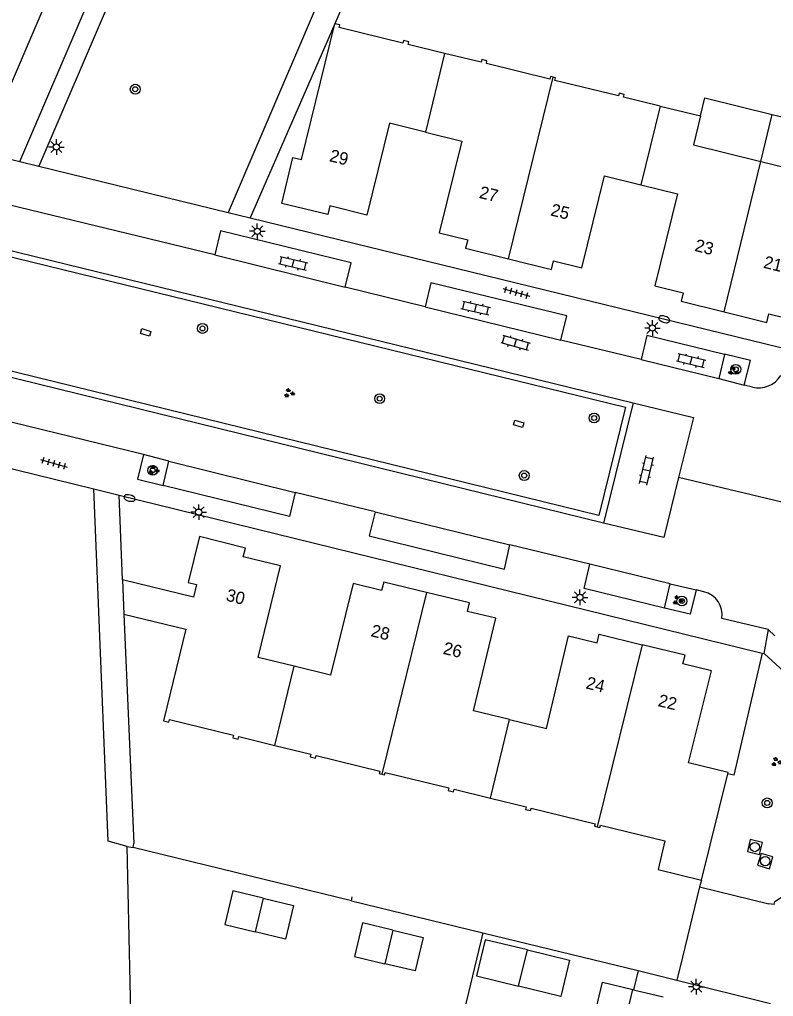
# Model space of a CAD drawing. Extents: x 125000 to 129004, y 397500 to 399008.
# Drawn here: x 126498.7 to 126559.6, y 398186.4 to 398265.2 of the extents above; entities that cross this region are included whole.
import ezdxf

# ---------------------------------------------------------------- set-up
doc = ezdxf.new("R2010")
doc.units = 0
for name, color, linetype in [('gg-afsc-erfafscheiding', 7, 'Continuous'), ('gg-afsc-hekwerk', 7, 'Continuous'), ('gg-afsc-muur', 7, 'Continuous'), ('gg-anno-huisnummerreeks BGT', 7, 'Continuous'), ('gg-bbg-bijgebouw', 7, 'Continuous'), ('gg-bbg-gedigitaliseerde bijgebouw', 7, 'Continuous'), ('gg-bbg-hoofdgebouw', 7, 'Continuous'), ('gg-bbg-luifel en loopbrug', 7, 'Continuous'), ('gg-bbg-tussenscheiding', 7, 'Continuous'), ('gg-knt-verharding', 7, 'Continuous'), ('gg-knt-verharding nz', 7, 'Continuous'), ('gt-grn-groengrens', 7, 'Continuous'), ('gt-grn-weggrens', 7, 'Continuous'), ('gt-symb-boom', 7, 'Continuous'), ('gt-symb-brandkraan', 7, 'Continuous'), ('gt-symb-groenvak', 7, 'Continuous'), ('gt-symb-klinker verharding', 7, 'Continuous'), ('gt-symb-kolk center center', 7, 'Continuous'), ('gt-symb-lichtmast', 7, 'Continuous'), ('gt-symb-rioolschacht', 7, 'Continuous'), ('gt-symb-tegel verharding', 7, 'Continuous')]:
    doc.layers.add(name, color=color, linetype=linetype)

# ---------------------------------------------------------------- blocks, each defined once
blk = doc.blocks.new('gt0-LMAST')
at = {"layer": 'gt-symb-lichtmast'}
for p, q in [((-0.182, 0.173), (-0.447, 0.438)), ((-0.005, 0.246), (-0.005, 0.621)), ((0.172, 0.173), (0.437, 0.438)), ((-0.255, -0.004), (-0.63, -0.004)), ((-0.182, -0.181), (-0.447, -0.446)), ((-0.005, -0.254), (-0.005, -0.629)), ((0.437, -0.446), (0.172, -0.181)), ((0.245, -0.004), (0.62, -0.004))]:
    blk.add_line(p, q, dxfattribs=at)
blk.add_circle((-0.005, -0.004), 0.25, dxfattribs=at)
blk = doc.blocks.new('gt0-KL1')
at = {"layer": 'gt-symb-klinker verharding'}
for p, q in [((-1.15, 0.3), (1.15, 0.3)), ((-1, -0.3), (-1, 0.3)), ((-0.5, 0.3), (-0.5, 0.45)), ((0, -0.3), (0, 0.3)), ((0.5, 0.3), (0.5, 0.45)), ((1, -0.3), (1, 0.3)), ((-1.15, -0.3), (1.15, -0.3)), ((-0.5, -0.45), (-0.5, -0.3)), ((0.5, -0.45), (0.5, -0.3))]:
    blk.add_line(p, q, dxfattribs=at)
blk = doc.blocks.new('gt0-GRVAK')
at = {"layer": 'gt-symb-groenvak'}
for p, q in [((-0.11, 0.189), (-0.228, 0.24)), ((-0.182, 0.153), (0.088, 0.153)), ((-0.091, 0.211), (-0.156, 0.322)), ((-0.047, 0.214), (-0.047, 0.393)), ((-0.004, 0.211), (0.061, 0.322)), ((0.015, 0.189), (0.133, 0.24)), ((0.262, -0.052), (0.197, 0.059)), ((0.305, -0.049), (0.305, 0.13)), ((0.349, -0.052), (0.414, 0.059)), ((-0.245, -0.228), (-0.363, -0.177)), ((-0.318, -0.264), (-0.047, -0.264)), ((-0.226, -0.206), (-0.291, -0.095)), ((-0.183, -0.203), (-0.183, -0.024)), ((-0.139, -0.206), (-0.074, -0.095)), ((-0.12, -0.228), (-0.002, -0.177)), ((0.243, -0.074), (0.125, -0.023)), ((0.17, -0.11), (0.441, -0.11)), ((0.368, -0.074), (0.486, -0.023))]:
    blk.add_line(p, q, dxfattribs=at)
blk = doc.blocks.new('gt0-BOOM')
at = {"layer": 'gt-symb-boom'}
for radius in [0.4, 0.2]:
    blk.add_circle((0, 0), radius, dxfattribs=at)
blk = doc.blocks.new('gt0-RS')
at = {"layer": 'gt-symb-rioolschacht'}
blk.add_lwpolyline([(-0.5, -0.5), (0.5, -0.5), (0.5, 0.5), (-0.5, 0.5)], close=True, dxfattribs=at)
blk.add_circle((0, 0), 0.375, dxfattribs=at)
blk = doc.blocks.new('gt0-KOLKCC')
at = {"layer": 'gt-symb-kolk center center'}
blk.add_lwpolyline([(-0.375, 0.2), (0.375, 0.2), (0.375, -0.2), (-0.375, -0.2)], close=True, dxfattribs=at)
blk = doc.blocks.new('gt0-BR')
at = {"layer": 'gt-symb-brandkraan'}
for centre, radius, start, end in [((-0.244, 0), 0.206, 107.56694, 252.43307), ((0.599, -2.664), 3, 106.89205, 107.56694), ((0, -0.691), 0.938, 73.10799, 106.89205), ((-0.599, -2.664), 3, 72.43309, 73.10799), ((0.244, 0), 0.206, 287.56695, 72.43309), ((0.599, 2.664), 3, 252.43307, 253.10797), ((0, 0.691), 0.938, 253.10797, 286.89206), ((-0.599, 2.664), 3, 286.89206, 287.56695)]:
    blk.add_arc(centre, radius, start, end, dxfattribs=at)
blk = doc.blocks.new('gt0-TEG1')
at = {"layer": 'gt-symb-tegel verharding'}
for p, q in [((-1.125, 0), (1.125, 0)), ((-0.9, -0.25), (-0.9, 0.25)), ((-0.45, -0.25), (-0.45, 0.25)), ((0, -0.25), (0, 0.25)), ((0.45, -0.25), (0.45, 0.25)), ((0.9, -0.25), (0.9, 0.25))]:
    blk.add_line(p, q, dxfattribs=at)

msp = doc.modelspace()

# ---------------------------------------------------------------- linework, layer by layer
at = {"layer": 'gg-afsc-erfafscheiding'}
for p, q in [((126530.085, 398278.427), (126524.158, 398264.837)), ((126524.158, 398264.837), (126517.334, 398249.183)), ((126507.141, 398217.221), (126507.957, 398198.733)), ((126558.655, 398214.074), (126556.351, 398204.237)), ((126507.415, 398198.481), (126507.893, 398198.414)), ((126525.501, 398194.112), (126536.118, 398191.524)), ((126536.118, 398191.524), (126530.205, 398167.154)), ((126536.118, 398191.524), (126548.626, 398188.475)), ((126548.626, 398188.475), (126548.275, 398186.937)), ((126548.626, 398188.475), (126551.761, 398187.711))]:
    msp.add_line(p, q, dxfattribs=at)
msp.add_lwpolyline([(126507.32, 398172.797), (126506.054, 398173.108), (126505.732, 398184.245), (126507.749, 398183.848), (126507.415, 398198.481)], dxfattribs=at)
at = {"layer": 'gg-afsc-hekwerk'}
for p, q in [((126556.351, 398204.237), (126555.863, 398204.347)), ((126553.736, 398195.771), (126553.6, 398195.242)), ((126553.6, 398195.242), (126552.211, 398189.553)), ((126553.6, 398195.242), (126559.178, 398193.847)), ((126552.211, 398189.553), (126551.761, 398187.711)), ((126551.761, 398187.711), (126559.318, 398185.826))]:
    msp.add_line(p, q, dxfattribs=at)
at = {"layer": 'gg-afsc-muur'}
for p, q in [((126507.036, 398219.989), (126506.755, 398226.822)), ((126507.893, 398198.414), (126507.957, 398198.733)), ((126525.501, 398194.112), (126507.893, 398198.414)), ((126525.501, 398194.112), (126525.565, 398194.431))]:
    msp.add_line(p, q, dxfattribs=at)
at = {"layer": 'gg-bbg-bijgebouw'}
for p, q in [((126548.21, 398186.953), (126548.275, 398186.937)), ((126548.275, 398186.937), (126550.649, 398186.364))]:
    msp.add_line(p, q, dxfattribs=at)
for points in [[(126518.388, 398194.314), (126515.936, 398194.9), (126515.289, 398192.195), (126517.741, 398191.609)], [(126518.388, 398194.314), (126520.84, 398193.727), (126520.193, 398191.022), (126517.741, 398191.609)], [(126528.853, 398191.737), (126526.402, 398192.326), (126525.752, 398189.621), (126528.203, 398189.033)], [(126528.853, 398191.737), (126531.303, 398191.148), (126530.653, 398188.445), (126528.203, 398189.033)], [(126547.554, 398184.239), (126545.104, 398184.831), (126545.761, 398187.543), (126548.21, 398186.953)]]:
    msp.add_lwpolyline(points, dxfattribs=at)
at = {"layer": 'gg-bbg-gedigitaliseerde bijgebouw'}
msp.add_line((126538.992, 398187.225), (126539.699, 398190.141), dxfattribs=at)
msp.add_lwpolyline([(126539.699, 398190.141), (126536.298, 398190.966), (126535.591, 398188.05), (126538.992, 398187.225)], dxfattribs=at)
at = {"layer": 'gg-bbg-hoofdgebouw'}
for p, q in [((126550.414, 398258.194), (126553.672, 398257.397)), ((126507.036, 398219.989), (126507.141, 398217.221)), ((126512.767, 398218.591), (126507.036, 398219.989)), ((126507.141, 398217.221), (126512.137, 398216.004)), ((126512.137, 398216.004), (126510.337, 398208.621)), ((126553.736, 398195.771), (126555.863, 398204.347))]:
    msp.add_line(p, q, dxfattribs=at)
for points in [[(126519.889, 398250.346), (126520.789, 398254.046), (126521.47, 398253.873), (126524.158, 398264.837)], [(126533.025, 398262.442), (126530.073, 398263.161), (126530.132, 398263.373), (126529.702, 398263.478), (126529.653, 398263.279), (126524.525, 398264.526), (126524.575, 398264.74), (126524.158, 398264.837)], [(126541.774, 398260.529), (126541.571, 398260.579), (126541.518, 398260.365), (126536.391, 398261.626), (126536.441, 398261.84), (126536.021, 398261.939), (126535.969, 398261.725), (126533.025, 398262.442)], [(126550.414, 398258.194), (126547.462, 398258.916), (126547.513, 398259.13), (126547.11, 398259.226), (126547.058, 398259.012), (126541.924, 398260.266), (126541.976, 398260.48), (126541.774, 398260.529)], [(126531.474, 398256.097), (126528.577, 398256.815), (126526.736, 398249.39), (126523.776, 398250.139), (126523.614, 398249.458), (126519.889, 398250.346)], [(126553.672, 398257.397), (126553.099, 398255.056), (126558.537, 398253.731)], [(126531.474, 398256.097), (126534.422, 398255.366), (126532.588, 398247.97), (126534.888, 398247.404), (126534.721, 398246.724), (126538.187, 398245.871)], [(126558.537, 398253.731), (126563.946, 398252.412), (126564.875, 398256.204)], [(126538.187, 398245.871), (126541.642, 398245.02), (126541.812, 398245.706), (126544.103, 398245.14), (126545.933, 398252.558), (126548.859, 398251.836)], [(126548.859, 398251.836), (126551.807, 398251.109), (126549.977, 398243.691), (126552.27, 398243.127), (126552.103, 398242.447), (126555.57, 398241.598)], [(126555.57, 398241.598), (126559.021, 398240.753), (126559.187, 398241.435), (126561.488, 398240.875), (126563.292, 398248.296), (126566.468, 398247.524)], [(126520.894, 398213.016), (126517.983, 398213.724), (126519.784, 398221.125), (126516.782, 398221.856), (126516.956, 398222.535), (126513.236, 398223.486), (126512.338, 398219.784), (126513.018, 398219.619), (126512.767, 398218.591)], [(126531.565, 398218.974), (126528.108, 398219.813), (126527.943, 398219.133), (126525.649, 398219.69), (126523.817, 398212.304), (126520.894, 398213.016)], [(126538.27, 398208.717), (126535.365, 398209.414), (126537.156, 398216.884), (126534.862, 398217.441), (126535.03, 398218.132), (126531.565, 398218.974)], [(126538.27, 398208.717), (126541.241, 398208.005), (126543.032, 398215.475), (126545.318, 398214.916), (126545.485, 398215.597), (126548.96, 398214.747)], [(126555.863, 398204.347), (126555.888, 398204.447), (126552.711, 398205.235), (126554.552, 398212.658), (126552.256, 398213.219), (126552.422, 398213.901), (126548.96, 398214.747)], [(126510.337, 398208.621), (126510.78, 398208.513), (126510.83, 398208.717), (126515.991, 398207.456), (126515.941, 398207.251), (126516.372, 398207.145), (126516.423, 398207.352), (126519.334, 398206.639)], [(126519.334, 398206.639), (126522.243, 398205.926), (126522.19, 398205.723), (126522.616, 398205.619), (126522.666, 398205.823), (126527.801, 398204.567), (126527.752, 398204.363), (126527.967, 398204.311)], [(126527.967, 398204.311), (126528.181, 398204.26), (126528.23, 398204.463), (126533.362, 398203.208), (126533.314, 398203.005), (126533.734, 398202.903), (126533.784, 398203.105), (126536.722, 398202.386)], [(126536.722, 398202.386), (126539.605, 398201.681), (126539.557, 398201.477), (126539.964, 398201.38), (126540.014, 398201.584), (126545.174, 398200.32), (126545.124, 398200.116), (126545.34, 398200.063)], [(126545.34, 398200.063), (126545.557, 398200.01), (126545.607, 398200.214), (126550.797, 398198.945), (126550.245, 398196.628), (126553.736, 398195.771)]]:
    msp.add_lwpolyline(points, dxfattribs=at)
at = {"layer": 'gg-bbg-luifel en loopbrug'}
for p, q in [((126558.537, 398253.731), (126559.462, 398257.526)), ((126559.462, 398257.526), (126564.875, 398256.204))]:
    msp.add_line(p, q, dxfattribs=at)
for points in [[(126553.672, 398257.397), (126554.028, 398258.854), (126559.462, 398257.526)], [(126539.699, 398190.141), (126543.101, 398189.315), (126542.393, 398186.4), (126538.992, 398187.225)]]:
    msp.add_lwpolyline(points, dxfattribs=at)
at = {"layer": 'gg-bbg-tussenscheiding'}
for p, q in [((126533.025, 398262.442), (126531.474, 398256.097)), ((126538.187, 398245.871), (126541.774, 398260.529)), ((126550.414, 398258.194), (126548.859, 398251.836)), ((126555.57, 398241.598), (126558.537, 398253.731)), ((126531.565, 398218.974), (126527.967, 398204.311)), ((126548.96, 398214.747), (126545.34, 398200.063)), ((126519.334, 398206.639), (126520.894, 398213.016)), ((126536.722, 398202.386), (126538.27, 398208.717)), ((126518.388, 398194.314), (126517.741, 398191.609)), ((126528.853, 398191.737), (126528.203, 398189.033)), ((126547.554, 398184.239), (126548.21, 398186.953))]:
    msp.add_line(p, q, dxfattribs=at)
at = {"layer": 'gg-knt-verharding'}
for p, q in [((126498.762, 398253.723), (126511.293, 398282.977)), ((126512.808, 398282.618), (126500.286, 398253.351)), ((126495.687, 398254.475), (126498.762, 398253.723)), ((126498.762, 398253.723), (126500.286, 398253.351)), ((126500.286, 398253.351), (126515.562, 398249.616)), ((126514.473, 398246.188), (126492.984, 398251.418)), ((126515.562, 398249.616), (126517.334, 398249.183)), ((126517.334, 398249.183), (126564.295, 398237.705)), ((126497.358, 398246.71), (126548.23, 398234.269)), ((126497.155, 398246.245), (126547.625, 398233.902)), ((126531.462, 398241.996), (126525, 398243.584)), ((126548.879, 398237.745), (126542.406, 398239.322)), ((126545.477, 398225.172), (126493.522, 398237.929)), ((126555.597, 398238.16), (126555.138, 398236.213)), ((126545.843, 398224.567), (126493.319, 398237.464)), ((126508.726, 398230.085), (126485.398, 398235.791)), ((126555.138, 398236.213), (126557.195, 398235.696)), ((126557.854, 398235.518), (126557.195, 398235.696)), ((126547.625, 398233.902), (126545.477, 398225.172)), ((126548.23, 398234.269), (126545.843, 398224.567)), ((126490.544, 398230.802), (126504.734, 398227.318)), ((126510.776, 398229.554), (126508.726, 398230.085)), ((126510.308, 398227.598), (126510.776, 398229.554)), ((126504.734, 398227.318), (126506.755, 398226.822)), ((126506.755, 398226.822), (126558.655, 398214.074)), ((126527.416, 398225.473), (126520.963, 398227.032)), ((126544.749, 398221.259), (126538.276, 398222.811)), ((126550.765, 398217.692), (126551.221, 398219.667)), ((126551.221, 398219.667), (126553.325, 398219.174)), ((126553.937, 398219.016), (126553.325, 398219.174)), ((126559.136, 398215.983), (126555.385, 398216.866)), ((126559.665, 398215.469), (126559.136, 398215.983)), ((126558.655, 398214.074), (126558.789, 398214.041)), ((126558.789, 398214.041), (126558.823, 398214.01))]:
    msp.add_line(p, q, dxfattribs=at)
for points in [[(126525, 398243.584), (126525.475, 398245.539), (126514.93, 398248.139), (126514.473, 398246.188)], [(126542.406, 398239.322), (126542.888, 398241.276), (126531.922, 398243.95), (126531.462, 398241.996)], [(126555.597, 398238.16), (126549.325, 398239.697), (126548.879, 398237.745)], [(126557.195, 398235.696), (126557.693, 398237.686), (126555.609, 398238.198), (126555.597, 398238.16)], [(126508.726, 398230.085), (126508.241, 398228.111), (126510.308, 398227.598)], [(126520.963, 398227.032), (126520.502, 398225.089), (126510.308, 398227.598)], [(126527.416, 398225.473), (126526.925, 398223.524), (126537.865, 398220.849), (126538.276, 398222.811)], [(126550.765, 398217.692), (126544.285, 398219.278), (126544.749, 398221.259)], [(126553.325, 398219.174), (126552.84, 398217.206), (126550.765, 398217.692)], [(126559.6, 398193.803), (126559.659, 398194.06), (126560.377, 398194.51), (126563.993, 398209.313), (126558.823, 398214.01)]]:
    msp.add_lwpolyline(points, dxfattribs=at)
for centre, radius, start, end in [((126558.346, 398237.544), 2.085, 256.35137, 329.28677), ((126553.538, 398217.185), 1.874, 350.21358, 77.70604)]:
    msp.add_arc(centre, radius, start, end, dxfattribs=at)
at = {"layer": 'gg-knt-verharding nz'}
for p, q in [((126514.473, 398246.188), (126525, 398243.584)), ((126531.462, 398241.996), (126542.406, 398239.322)), ((126548.879, 398237.745), (126555.138, 398236.213)), ((126510.776, 398229.554), (126520.963, 398227.032)), ((126527.416, 398225.473), (126538.276, 398222.811)), ((126551.221, 398219.667), (126544.749, 398221.259))]:
    msp.add_line(p, q, dxfattribs=at)
for points in [[(126548.23, 398234.269), (126553.098, 398233.078), (126551.902, 398228.239)], [(126551.902, 398228.239), (126550.706, 398223.399), (126545.843, 398224.567)]]:
    msp.add_lwpolyline(points, dxfattribs=at)
at = {"layer": 'gt-grn-groengrens'}
for p, q in [((126495.687, 398254.475), (126508.224, 398283.734)), ((126528.097, 398278.909), (126515.562, 398249.616)), ((126559.6, 398193.803), (126559.178, 398193.847))]:
    msp.add_line(p, q, dxfattribs=at)
msp.add_lwpolyline([(126507.415, 398198.481), (126505.872, 398198.908), (126504.734, 398227.318)], dxfattribs=at)
at = {"layer": 'gt-grn-weggrens'}
for p, q in [((126562.176, 398225.781), (126551.902, 398228.239)), ((126559.136, 398215.983), (126558.789, 398214.041))]:
    msp.add_line(p, q, dxfattribs=at)

# ---------------------------------------------------------------- block references
at = {"layer": 'gt-symb-boom'}
for p in [(126508.068, 398259.553), (126513.491, 398240.262), (126556.514, 398236.965), (126527.786, 398234.6), (126545.086, 398233.036), (126509.469, 398228.818), (126539.449, 398228.396), (126552.165, 398218.278), (126559.05, 398201.997)]:
    msp.add_blockref('gt0-BOOM', p, dxfattribs=at)
at = {"layer": 'gt-symb-brandkraan'}
for p, rotation in [((126550.745, 398241.003), 161.32941658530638), ((126507.607, 398226.584), 166.46414363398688)]:
    msp.add_blockref('gt0-BR', p, dxfattribs=dict(at, rotation=rotation))
at = {"layer": 'gt-symb-groenvak', "rotation": -15.71725244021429}
msp.add_blockref('gt0-GRVAK', (126556.302, 398236.813), dxfattribs=at)
at = {"layer": 'gt-symb-groenvak'}
for p in [(126520.479, 398235.045), (126509.561, 398228.834), (126551.814, 398218.347), (126559.784, 398205.3)]:
    msp.add_blockref('gt0-GRVAK', p, dxfattribs=at)
at = {"layer": 'gt-symb-klinker verharding'}
for p, rotation in [((126520.806, 398245.517), -13.174926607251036), ((126535.533, 398241.912), -13.174926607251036), ((126538.736, 398239.108), -15.7172524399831), ((126552.915, 398237.674), -13.174926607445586), ((126549.312, 398228.819), 76.82507339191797)]:
    msp.add_blockref('gt0-KL1', p, dxfattribs=dict(at, rotation=rotation))
at = {"layer": 'gt-symb-kolk center center'}
for p, rotation in [((126508.907, 398239.943), -17.149043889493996), ((126539.004, 398232.568), -15.71725244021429)]:
    msp.add_blockref('gt0-KOLKCC', p, dxfattribs=dict(at, rotation=rotation))
at = {"layer": 'gt-symb-lichtmast'}
for p in [(126501.708, 398254.896), (126517.918, 398248.1), (126549.794, 398240.299), (126513.188, 398225.45), (126543.946, 398218.575), (126553.336, 398187.184)]:
    msp.add_blockref('gt0-LMAST', p, dxfattribs=at)
at = {"layer": 'gt-symb-rioolschacht'}
for p, rotation in [((126558.053, 398198.441), -13.952823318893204), ((126558.888, 398197.303), -16.567466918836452)]:
    msp.add_blockref('gt0-RS', p, dxfattribs=dict(at, rotation=rotation))
at = {"layer": 'gt-symb-tegel verharding', "rotation": -15.71725244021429}
for p in [(126538.804, 398243.166), (126501.503, 398229.391)]:
    msp.add_blockref('gt0-TEG1', p, dxfattribs=at)

# ---------------------------------------------------------------- texts
at = {"layer": 'gg-anno-huisnummerreeks BGT'}
for s, rotation, p in [('29', 345.8, (126523.669, 398253.76)), ('27', 346.2, (126535.753, 398250.796)), ('25', 346.1, (126541.509, 398249.384)), ('23', 346.2, (126553.14, 398246.518)), ('21', 346.3, (126558.685, 398245.163)), ('30', 345.7, (126515.324, 398218.327)), ('28', 346.4, (126527.015, 398215.447)), ('26', 346.4, (126532.836, 398214.034)), ('24', 346.2, (126544.361, 398211.239)), ('22', 346.3, (126550.178, 398209.816))]:
    msp.add_text(s, height=1, rotation=rotation, dxfattribs=at).set_placement(p)

doc.saveas('drawing.dxf')
